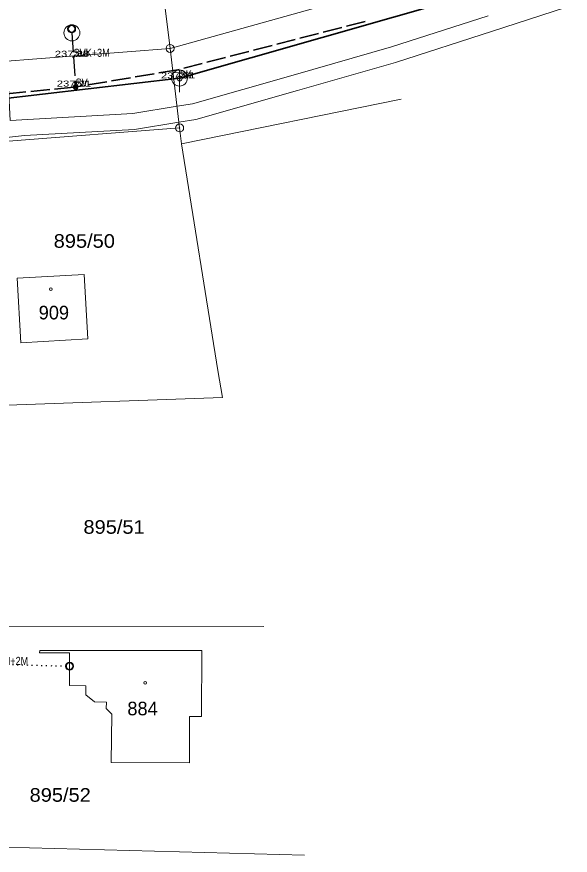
# Model space of a CAD drawing. Extents: x -686207 to -681951, y -1020493 to -1017811.
# Drawn here: x -682347.9 to -682278.7, y -1019178 to -1019073.2 of the extents above; entities that cross this region are included whole.
import ezdxf
from ezdxf.enums import TextEntityAlignment as Align

# ---------------------------------------------------------------- set-up
doc = ezdxf.new("R2010")
doc.units = 0
doc.header["$LTSCALE"] = 0.4
doc.header["$PDMODE"] = 32
doc.header["$PDSIZE"] = 0.2
doc.linetypes.add('DOTTED', pattern=[1.5, 0.3, -1.2])
doc.linetypes.add('LONG_DASHED', pattern=[7.5, 6, -1.5])
for name, color, linetype, lineweight in [('1', 7, 'Continuous', 13), ('10', 7, 'Continuous', 13), ('12', 7, 'Continuous', 13), ('13', 7, 'Continuous', 13), ('3', 7, 'Continuous', 13), ('35', 7, 'LONG_DASHED', 35), ('4', 7, 'Continuous', 13), ('45', 7, 'Continuous', 35), ('5', 7, 'Continuous', 13), ('50', 7, 'LONG_DASHED', 25), ('51', 7, 'DOTTED', 25), ('8', 7, 'Continuous', 13)]:
    doc.layers.add(name, color=color, linetype=linetype, lineweight=lineweight)
doc.layers.add('2', color=7, linetype='Continuous')

msp = doc.modelspace()

# ---------------------------------------------------------------- linework, layer by layer
at = {"layer": '1'}
for p, q in [((-682302.99, -1019070), (-682328.73, -1019077.2)), ((-682364.62, -1019080), (-682328.73, -1019077.2)), ((-682328.73, -1019077.2), (-682327.53, -1019087.13)), ((-682327.29, -1019089.11), (-682299.84, -1019083.54)), ((-682348.9, -1019088.77), (-682327.53, -1019087.13)), ((-682327.53, -1019087.13), (-682327.29, -1019089.11)), ((-682352.97, -1019121.88), (-682322.17, -1019120.8)), ((-682351.19, -1019149.46), (-682317.03, -1019149.42)), ((-682311.91, -1019177.99), (-682349.42, -1019176.97))]:
    msp.add_line(p, q, dxfattribs=at)
for points in [[(-682331.26, -1019059.77), (-682330.85, -1019063.15), (-682329.75, -1019068.81), (-682328.73, -1019077.2)], [(-682322.17, -1019120.8), (-682322.78, -1019117.42), (-682327.29, -1019089.11)]]:
    msp.add_lwpolyline(points, dxfattribs=at)
for points in [[(-682347.84, -1019105.88), (-682339.46, -1019105.42), (-682338.99, -1019113.48), (-682347.39, -1019113.96)], [(-682345.02, -1019152.4), (-682324.76, -1019152.43), (-682324.78, -1019160.64), (-682326.29, -1019160.64), (-682326.3, -1019166.43), (-682336.07, -1019166.42), (-682336.02, -1019160.36), (-682336.7, -1019159.64), (-682336.67, -1019158.86), (-682338.17, -1019158.84), (-682339.26, -1019157.95), (-682339.27, -1019156.82), (-682341.28, -1019156.8), (-682341.29, -1019152.71), (-682345.03, -1019152.7)]]:
    msp.add_lwpolyline(points, close=True, dxfattribs=at)
for p in [(-682340.79, -1019078.24), (-682327.53, -1019080.95), (-682340.54, -1019081.96)]:
    msp.add_point(p, dxfattribs=at)
at = {"layer": '10'}
msp.add_line((-682327.552, -1019079.892), (-682327.552, -1019082.64), dxfattribs=at)
msp.add_lwpolyline([(-682340.39, -1019082.46), (-682340.69, -1019081.46), (-682340.39, -1019081.46), (-682340.69, -1019082.46)], close=True, dxfattribs=at)
for centre, radius in [((-682340.991, -1019075.247), 1), ((-682327.552, -1019080.893), 1.0002)]:
    msp.add_circle(centre, radius, dxfattribs=at)
at = {"layer": '12'}
for centre, radius in [((-682341.025, -1019074.748), 0.5), ((-682341.025, -1019074.748), 0.4), ((-682340.537, -1019082.01), 0.3), ((-682340.537, -1019082.01), 0.2), ((-682340.537, -1019082.01), 0.1), ((-682341.286, -1019154.371), 0.5), ((-682341.286, -1019154.371), 0.4)]:
    msp.add_circle(centre, radius, dxfattribs=at)
at = {"layer": '13'}
for points in [[(-682349.55, -1019088.38), (-682346.92, -1019088.09), (-682333.16, -1019087.31), (-682327.62, -1019086.4), (-682325.5, -1019086.06), (-682312.79, -1019082.47), (-682300.54, -1019078.95), (-682288.46, -1019075.05), (-682262.6, -1019066.62)], [(-682288.98, -1019073.11), (-682301.07, -1019077.01), (-682313.33, -1019080.55), (-682325.94, -1019084.1), (-682327.86, -1019084.42), (-682333.38, -1019085.31), (-682348.69, -1019086.18), (-682349.08, -1019078.79), (-682351.07, -1019078.94), (-682350.69, -1019086.22), (-682357.5, -1019087.3), (-682364, -1019087.49), (-682382.35, -1019088.3), (-682390.41, -1019088.77), (-682393.96, -1019088.76), (-682393.97, -1019082.28), (-682393.49, -1019071.55)]]:
    msp.add_lwpolyline(points, dxfattribs=at)
msp.add_circle((-682327.53, -1019080.95), 0.3, dxfattribs=at)
at = {"layer": '35'}
msp.add_line((-682361.069, -1019084.049), (-682340.537, -1019082.01), dxfattribs=at)
msp.add_lwpolyline([(-682304.361, -1019073.831), (-682327.75, -1019079.855), (-682340.537, -1019082.01)], dxfattribs=at)
at = {"layer": '45'}
for p, q in [((-682327.552, -1019080.892), (-682285.616, -1019068.942)), ((-682360.594, -1019084.769), (-682327.552, -1019080.892))]:
    msp.add_line(p, q, dxfattribs=at)
at = {"layer": '5'}
for centre in [(-682343.6368, -1019107.2692), (-682331.8468, -1019156.4592)]:
    msp.add_circle(centre, 0.175, dxfattribs=at)
at = {"layer": '50'}
msp.add_line((-682340.54, -1019081.96), (-682340.537, -1019082.01), dxfattribs=at)
msp.add_lwpolyline([(-682340.991, -1019075.247), (-682340.79, -1019078.24), (-682340.54, -1019081.96)], dxfattribs=at)
at = {"layer": '51'}
for p, q in [((-682340.991, -1019075.247), (-682341.025, -1019074.748)), ((-682349.031, -1019154.156), (-682341.286, -1019154.371))]:
    msp.add_line(p, q, dxfattribs=at)
at = {"layer": '8'}
for centre, radius in [((-682328.73, -1019077.1999), 0.5), ((-682328.73, -1019077.1999), 0.0303), ((-682327.53, -1019087.1299), 0.5), ((-682327.53, -1019087.1299), 0.0303)]:
    msp.add_circle(centre, radius, dxfattribs=at)

# ---------------------------------------------------------------- texts
at = {"layer": '2'}
for s, height, p in [('211', 0.75, (-682340.79, -1019078.24)), ('212', 0.75, (-682327.53, -1019080.95)), ('210', 0.75, (-682340.54, -1019081.96)), ('909', 1.7, (-682345.144, -1019111.049)), ('884', 1.7, (-682334.064, -1019160.51))]:
    msp.add_text(s, height=height, dxfattribs=at).set_placement(p)
at = {"layer": '2', "width": 1.1}
for s, p in [('895/50', (-682343.27, -1019102.1)), ('895/51', (-682339.55, -1019137.83)), ('895/52', (-682346.28, -1019171.309))]:
    msp.add_text(s, height=1.7, dxfattribs=at).set_placement(p)
at = {"layer": '3', "width": 1.4}
for s, p in [('237 88 ', (-682340.79, -1019078.24)), ('237 51 ', (-682327.53, -1019080.95)), ('237 71 ', (-682340.54, -1019081.96))]:
    msp.add_text(s, height=0.75, dxfattribs=at).set_placement(p, align=Align.CENTER)
at = {"layer": '4', "width": 0.85}
for s, p in [('SVK+3M', (-682340.79, -1019078.24)), ('SK', (-682327.53, -1019080.95)), ('SV', (-682340.54, -1019081.96)), ('SVH+2M', (-682351.03, -1019154.21))]:
    msp.add_text(s, height=1, dxfattribs=at).set_placement(p)

doc.saveas('drawing.dxf')
